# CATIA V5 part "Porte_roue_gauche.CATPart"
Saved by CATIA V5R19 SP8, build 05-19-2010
Part number: Porte_roue_gauche
Bounding box of the stored display mesh (mm): x -960 to -840, y 0 to 1559.994, z -909.972 to -140
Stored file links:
  G:\EU_thinkMotion\CFAO_2010\MMS_groupe2\MMS_groupe2\OK\mmartini\mmartiniCFAO\Porte_roue_gauche.CATPart
  C:\Users\Mathieu Martini\Desktop\CFAO\Animation\CFAO.CATProduct
  G:\EU_thinkMotion\CFAO_2010\MMS_groupe2\MMS_groupe2\OK\mmartini\mmartiniCFAO\Squelette.CATPart
  G:\EU_thinkMotion\CFAO_2010\MMS_groupe2\MMS_groupe2\OK\mmartini\mmartiniCFAO\Jambe_gauche_roue.CATPart
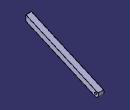
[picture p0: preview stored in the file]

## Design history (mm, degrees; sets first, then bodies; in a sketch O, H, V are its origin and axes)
External parameters (linked from other documents)
  External.diametre_verin = 120 mm
  External.diametre_canon = 150 mm
AxisSystem1: origin (0, 0, 0), X (1, 0, 0), Y (0, 1, 0), Z (0, 0, 1)
Set1
  Sketch1 on Plane1, origin (0, 0, 0), H (-1, 0, 0), V (0, 0, 1)
    line L1 (840, -140) -> (960, -140)
    line L2 (960, -140) -> (960, -260)
    line L3 (960, -260) -> (840, -260)
    line L4 (840, -260) -> (840, -140)
    reference projected line E1 through (0, -200) direction (-1, 0) from Line1
    reference intersected line E2 through (825, 0) direction (0, -1) from Plane2
    distance L3 L1 = 120 {= External.diametre_verin}
    distance L1 E1 = 60 {= External.diametre_verin /2}
    distance L4 L2 = 120 {= External.diametre_verin}
    distance E2 L4 = 15 {= External.diametre_canon /10}
    horizontal: L1 H, L3 H
    vertical: L2 V, L4 V
  Sketch2 on face of DatumSurface1, origin (-840, 0, 0), H (0, -1, 0), V (0, 0, 1)
    axis line L1 (-1500, -850) -> (540.1492, 39.2958)
    point P1 (-1500, -850)
    reference projected point E1 (-1500, -850) from Line2
    reference projected point E2 (450, 0) from Line3
    line L2 (-1476.0249, -905.0018) -> (0, -261.6063)
    point P4 (0, -261.6063)
    reference intersected line E3 through (0, 0) direction (0, -1) from Plane1
    line L3 (0, -130.7014) -> (-1523.9751, -794.9982)
    point P5 (0, -130.7014)
    reference intersected line E4 through (0, 0) direction (0, -1) from Plane1
    line L4 (0, -130.7014) -> (0, -261.6063)
    arc A1 centre (-1500, -850) radius 60 from (-1523.9751, -794.9982) to (-1476.0249, -905.0018) ccw
    distance L2 L1 = 60 {= External.diametre_verin /2}
    distance L3 L1 = 60 {= External.diametre_verin /2}
    coincidence: P1 E1, L1 E2, E3 P4, P5 E4
    vertical: L4 V
    tangency: A1 L3
Set2
  Plane1: linked copy from another document
  Line1 "Droite_plan_de_construction_verin": linked copy from another document
  Plane2 "Plan_jambe_gauche_roue": linked copy from another document
  DatumSurface1: linked copy from another document
  Line2 "axe_roue": linked copy from another document
  Line3 "axe_berceau_jambe_roue": linked copy from another document
Body1 (main body)
  SolidCombine1: FirstComponentProfile Sketch1, FirstComponentDirection Sketch2.L2, SecondComponentProfile Sketch2, SecondComponentDirection Sketch2
  Sketch3 on face of SolidCombine1 from Sketch1.L2, origin (-960, 0, 0), H (0, -1, 0), V (0, 0, 1)
    circle A1 centre (-1500, -850) radius 25
    point P1 (-1500, -850)
    reference projected point E1 (-1500, -850) from Line2
    radius A1 = 25 {= External.diametre_canon /6}
    coincidence: P1 E1
  Pocket1: profile Sketch3, direction (1, 0, 0), through (limit type 6)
